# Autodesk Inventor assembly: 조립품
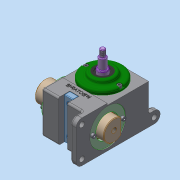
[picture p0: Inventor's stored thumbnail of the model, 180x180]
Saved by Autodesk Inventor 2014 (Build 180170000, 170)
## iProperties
Created: 2023-09
Part Number: 조립품
Document SubType Name: Assembly
Designer: dg
Author: dg
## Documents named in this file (11)
- C:\Users\dg\Desktop\730906V1007\조립품.iam
- C:\Users\dg\Desktop\730906V1007\본체.ipt
- C:\Users\dg\Desktop\730906V1007\가이드 부시.ipt
- C:\Users\dg\Desktop\730906V1007\래크.ipt
- C:\Users\dg\Desktop\730906V1007\베어링 6003.ipt
- C:\Users\dg\Desktop\730906V1007\볼트 M4.ipt
- C:\Users\dg\Desktop\730906V1007\부시 커버.ipt
- C:\Users\dg\Desktop\730906V1007\스톱퍼.ipt
- C:\Users\dg\Desktop\730906V1007\앞커버.ipt
- C:\Users\dg\Desktop\730906V1007\오일 실 17 30 5.ipt
- C:\Users\dg\Desktop\730906V1007\피니언.ipt
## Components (3 placed, 2 different names)
1. 가이드 부시:1
2. 피니언:1
3. 가이드 부시:2
